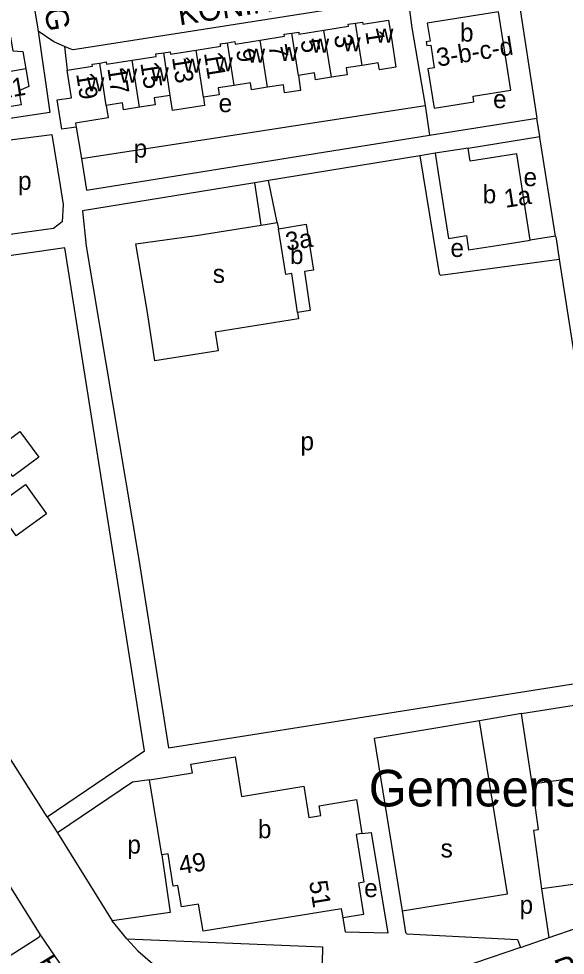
# Model space of a CAD drawing. Extents: x 159675 to 162108, y 386471 to 388472.
# Drawn here: x 160527.6 to 160647.4, y 386875.3 to 387080.5 of the extents above; entities that cross this region are included whole.
import ezdxf

# ---------------------------------------------------------------- set-up
doc = ezdxf.new("R2010")
doc.units = 0
for name, color, linetype in [('BLT_Basislijn', 7, 'Continuous'), ('BLT_Bebouwing', 7, 'Continuous'), ('BLT_Bebouwing_beschrifting', 7, 'Continuous'), ('BLT_Centroide', 7, 'Continuous'), ('BLT_Huisnummer', 7, 'Continuous'), ('BLT_Huisnummer_ tussenligend', 7, 'Continuous'), ('BLT_Huisnummer_reeks', 7, 'Continuous'), ('BLT_Onderverdeling_panden', 7, 'Continuous'), ('BLT_Straatnaam', 7, 'Continuous'), ('BLT_Vlakafsluiter', 7, 'Continuous')]:
    doc.layers.add(name, color=color, linetype=linetype)

msp = doc.modelspace()

# ---------------------------------------------------------------- linework, layer by layer
at = {"layer": 'BLT_Basislijn'}
for p, q in [((160537.63, 387074.35), (160538.2, 387069.22)), ((160541.3, 387049.83), (160616.69, 387061.42)), ((160616.69, 387061.42), (160617.66, 387054.93)), ((160540.15, 387056.72), (160541.3, 387049.83)), ((160617.66, 387054.93), (160641.18, 387058.71)), ((160641.8, 387054.69), (160641.18, 387058.71)), ((160626.09, 387052.12), (160641.8, 387054.69)), ((160618.89, 387051.01), (160615.55, 387050.46)), ((160615.55, 387050.46), (160582.31, 387045.02)), ((160582.31, 387045.02), (160579.33, 387044.54)), ((160584.25, 387035.83), (160582.31, 387045.02)), ((160580.71, 387035.26), (160584.25, 387035.83)), ((160584.25, 387035.83), (160584.54, 387034.45)), ((160645.29, 387032.81), (160639.7, 387031.95)), ((160646.04, 387027.79), (160660.27, 386936.54)), ((160637.8, 386928.26), (160660.96, 386931.98)), ((160640.15, 386912.84), (160637.8, 386928.26)), ((160533.79, 386905.62), (160536.05, 386902.11)), ((160536.05, 386902.11), (160548.06, 386882.84)), ((160643.91, 386879.19), (160642.29, 386889.86)), ((160551.24, 386878.93), (160548.06, 386882.84)), ((160637.62, 386877.04), (160643.91, 386879.19))]:
    msp.add_line(p, q, dxfattribs=at)
for points in [[(160525.82, 387114.65), (160525.96, 387113.82), (160528.15, 387100), (160531.84, 387077.71)], [(160612.92, 387085.16), (160631.58, 387088.2), (160635.7, 387088.25), (160636.9, 387086.77), (160641.18, 387058.71)], [(160612.92, 387085.16), (160539.47, 387073.63), (160538.99, 387073.76), (160537.63, 387074.35)], [(160612.92, 387085.16), (160613.78, 387078.48), (160616.69, 387061.42)], [(160531.84, 387077.71), (160534.38, 387059.89), (160513.51, 387056.76), (160514.73, 387049.16)], [(160537.63, 387074.35), (160535.24, 387075.38), (160531.84, 387077.71)], [(160536.69, 387043.96), (160537.33, 387039.73), (160537.06, 387035.97), (160535.21, 387034.49), (160522.41, 387032.72), (160519.35, 387053.09), (160534.86, 387055.11), (160536.69, 387043.96)], [(160541.3, 387049.83), (160542.44, 387042.9), (160617.66, 387054.93)], [(160645.29, 387032.81), (160641.84, 387054.43), (160641.8, 387054.69)], [(160615.55, 387050.46), (160619.76, 387024.57), (160620.02, 387024.3), (160646.04, 387027.79)], [(160579.33, 387044.54), (160541.58, 387038.36), (160542.39, 387030.6), (160553.88, 386962.03), (160560.43, 386920.74), (160660.27, 386936.54)], [(160588.73, 387016.11), (160588.95, 387014.72), (160570.67, 387011.82), (160571.31, 387007.69), (160557.43, 387005.49), (160555.72, 387016.54), (160553.27, 387031.17), (160566.47, 387032.97), (160580.71, 387035.26), (160580.4, 387037.26), (160579.33, 387044.54)], [(160645.29, 387032.81), (160645.38, 387032.21), (160646.04, 387027.79)], [(160533.79, 386905.62), (160555.12, 386920.11), (160537.7, 387030.3), (160500, 387024.88), (160461.83, 387019.07)], [(160533.79, 386905.62), (160515.13, 386934.8), (160500, 386958.89), (160461.83, 387019.07)], [(160637.8, 386928.26), (160628.58, 386926.69)], [(160628.58, 386926.69), (160605.53, 386922.76), (160611.64, 386885.01)], [(160611.64, 386885.01), (160634.73, 386888.75), (160628.58, 386926.69)], [(160505.85, 386921.44), (160507.66, 386919.05), (160532.28, 386879.76)], [(160556.25, 386913.76), (160552.5, 386913.2), (160536.05, 386902.11)], [(160643.91, 386879.19), (160645.32, 386879.67), (160662.54, 386885.53), (160665.02, 386887.2), (160665.65, 386887.94), (160666.08, 386888.6), (160667.09, 386892.03), (160665.4, 386903.23)], [(160602.82, 386901.96), (160604.84, 386902.22), (160608.49, 386880.15), (160599.2, 386880.34), (160598.68, 386883.49)], [(160558.92, 386897.27), (160560.78, 386884.7), (160548.06, 386882.84)], [(160611.64, 386885.01), (160612.41, 386880.27), (160612.66, 386880.01), (160636.93, 386878.73), (160637.62, 386877.04)], [(160532.28, 386879.76), (160531.96, 386879.22), (160509.46, 386864.89), (160508.91, 386864.54)], [(160551.24, 386878.93), (160553.72, 386876.27), (160558.48, 386872.1), (160561.42, 386869.96), (160570.27, 386865.5), (160581.17, 386862.81), (160588.59, 386862.35), (160593.86, 386862.86)], [(160551.24, 386878.93), (160594.19, 386877.18), (160593.86, 386862.86)], [(160637.62, 386877.04), (160598.11, 386863.6), (160593.86, 386862.86)]]:
    msp.add_lwpolyline(points, dxfattribs=at)
for points in [[(160522.1, 386985.83), (160527.79, 386990.06), (160532.01, 386984.39), (160526.31, 386980.16)], [(160522.38, 386973.66), (160529.03, 386978.46), (160533.69, 386971.99), (160527.03, 386967.2)]]:
    msp.add_lwpolyline(points, close=True, dxfattribs=at)
at = {"layer": 'BLT_Bebouwing'}
for p, q in [((160626.09, 387052.12), (160618.89, 387051.01)), ((160558.92, 386897.27), (160556.25, 386913.76))]:
    msp.add_line(p, q, dxfattribs=at)
for points in [[(160632.76, 387081.95), (160617.16, 387079.46), (160617.79, 387075.55), (160616.9, 387075.41), (160617.04, 387074.56), (160617.9, 387074.69), (160618.7, 387069.68), (160617.3, 387069.46), (160618.68, 387060.87), (160627.39, 387062.26), (160627.19, 387063.5), (160635.49, 387064.83), (160632.76, 387081.95)], [(160594.5, 387077.96), (160599.87, 387078.8), (160599.81, 387079.24), (160601.44, 387079.5)], [(160601.44, 387079.5), (160602.95, 387079.74), (160603.02, 387079.28), (160608.65, 387080.16), (160609.43, 387075.22), (160610.27, 387069.84), (160606.66, 387069.27), (160606.42, 387070.79), (160602.89, 387070.23)], [(160580.48, 387075.76), (160585.85, 387076.61), (160585.79, 387077.04), (160587.43, 387077.29)], [(160587.43, 387077.29), (160588.96, 387077.53), (160589.02, 387077.1), (160594.5, 387077.96)], [(160525.75, 387076.43), (160526.26, 387073.41), (160528.49, 387073.27), (160529.14, 387069.45)], [(160566.44, 387073.59), (160571.85, 387074.43), (160571.77, 387074.96), (160573.37, 387075.21)], [(160573.37, 387075.21), (160574.96, 387075.46), (160575.05, 387074.91), (160580.48, 387075.76)], [(160559.35, 387073.01), (160560.8, 387073.23), (160560.88, 387072.71), (160566.44, 387073.59)], [(160545.34, 387070.75), (160546.77, 387070.98), (160546.84, 387070.5), (160552.42, 387071.38)], [(160552.42, 387071.38), (160557.71, 387072.21), (160557.63, 387072.74), (160559.35, 387073.01)], [(160529.14, 387069.45), (160529.78, 387065.63), (160527.56, 387064.66), (160528.08, 387061.58), (160515.02, 387059.38), (160514.4, 387063.25), (160518.35, 387063.88), (160517.77, 387067.54)], [(160540.15, 387056.72), (160537.02, 387056.23), (160536.01, 387062.67), (160539.15, 387063.16), (160538.2, 387069.22)], [(160538.2, 387069.22), (160543.71, 387070.08), (160543.65, 387070.49), (160545.34, 387070.75)], [(160602.89, 387070.23), (160599.36, 387069.68), (160599.59, 387068.18), (160596.12, 387067.63)], [(160588.88, 387068.04), (160589.33, 387064.77), (160585.86, 387064.23), (160585.59, 387065.99), (160582.09, 387065.44)], [(160596.12, 387067.63), (160592.64, 387067.09), (160592.4, 387068.59), (160588.88, 387068.04)], [(160574.84, 387065.84), (160571.31, 387065.29), (160571.55, 387063.8), (160568.06, 387063.25)], [(160582.09, 387065.44), (160578.6, 387064.89), (160578.37, 387066.4), (160574.84, 387065.84)], [(160560.81, 387063.65), (160557.29, 387063.1), (160557.52, 387061.6), (160554.04, 387061.05)], [(160568.06, 387063.25), (160568.3, 387061.45), (160561.29, 387060.35), (160560.81, 387063.65)], [(160546.76, 387061.45), (160547.19, 387058.72), (160540.01, 387057.6), (160540.15, 387056.72)], [(160554.04, 387061.05), (160550.55, 387060.5), (160550.31, 387062.01), (160546.76, 387061.45)], [(160618.89, 387051.01), (160619.7, 387045.78), (160621.78, 387032.33), (160625.72, 387032.94), (160626.19, 387029.86), (160634.76, 387031.18), (160639.7, 387031.95)], [(160639.7, 387031.95), (160636.78, 387050.85), (160626.53, 387049.27), (160626.09, 387052.12)], [(160584.54, 387034.45), (160590.62, 387035.42), (160592.23, 387025.37), (160590.22, 387025.05)], [(160588.73, 387016.11), (160587.45, 387024.64), (160586.14, 387024.4), (160584.54, 387034.45)], [(160590.22, 387025.05), (160591.5, 387016.52), (160588.73, 387016.11)], [(160556.25, 386913.76), (160565.64, 386915.28), (160565.33, 386917.19), (160575.02, 386918.76), (160576.43, 386910.1), (160590.06, 386912.31), (160591.16, 386905.5), (160593.82, 386905.93), (160593.47, 386908.07), (160601.62, 386909.39), (160602.82, 386901.96)], [(160640.15, 386912.84), (160650.08, 386914.23), (160650.32, 386912.46), (160656.1, 386913.26), (160656.26, 386912.12), (160657.48, 386912.29)], [(160642.29, 386889.86), (160640.49, 386902.69), (160641.54, 386902.84), (160640.15, 386912.84)], [(160602.82, 386901.96), (160601.55, 386901.76), (160603.25, 386891.29), (160602.05, 386891.1), (160603.17, 386884.22), (160598.68, 386883.49)], [(160659.66, 386902.43), (160659.72, 386902.05), (160657.82, 386901.78), (160659.16, 386892.21), (160642.29, 386889.86)], [(160598.68, 386883.49), (160598.36, 386885.48), (160567.98, 386880.55), (160567.02, 386886.51), (160563.24, 386885.9), (160562.47, 386890.61), (160561.46, 386890.45), (160560.32, 386897.5), (160558.92, 386897.27)]]:
    msp.add_lwpolyline(points, dxfattribs=at)
at = {"layer": 'BLT_Onderverdeling_panden'}
for p, q in [((160602.89, 387070.23), (160601.44, 387079.5)), ((160588.88, 387068.04), (160587.43, 387077.29)), ((160596.12, 387067.63), (160594.5, 387077.96)), ((160574.84, 387065.84), (160573.37, 387075.21)), ((160582.09, 387065.44), (160580.48, 387075.76)), ((160568.06, 387063.25), (160566.44, 387073.59)), ((160554.04, 387061.05), (160552.42, 387071.38)), ((160560.81, 387063.65), (160559.35, 387073.01)), ((160529.14, 387069.45), (160517.77, 387067.54)), ((160546.76, 387061.45), (160545.34, 387070.75))]:
    msp.add_line(p, q, dxfattribs=at)
at = {"layer": 'BLT_Vlakafsluiter'}
msp.add_line((160532.28, 386879.76), (160539.78, 386868.77), dxfattribs=at)

# ---------------------------------------------------------------- texts
at = {"layer": 'BLT_Bebouwing_beschrifting'}
msp.add_text('Gemeenschapshuis', height=8, dxfattribs=at).set_placement((160604.33, 386907.91))
at = {"layer": 'BLT_Centroide'}
for s, p in [('b', (160624.33, 387075.44)), ('w', (160605.86, 387075.2)), ('w', (160591.77, 387073.02)), ('w', (160598.69, 387073.33)), ('w', (160577.73, 387070.81)), ('w', (160584.91, 387071.17)), ('w', (160563.7, 387068.62)), ('w', (160570.64, 387068.95)), ('w', (160549.69, 387066.42)), ('w', (160556.61, 387066.73)), ('w', (160542.5, 387064.58)), ('e', (160571.4, 387059.99)), ('e', (160631.58, 387060.88)), ('p', (160552.76, 387050.04)), ('e', (160638.26, 387043.78)), ('p', (160527.41, 387042.97)), ('b', (160629.3, 387040.02)), ('b', (160587.04, 387026.73)), ('e', (160622.23, 387028.27)), ('s', (160570.12, 387022.59)), ('p', (160589.35, 386985.92)), ('b', (160580.01, 386900.94)), ('p', (160551.39, 386897.57)), ('s', (160620.08, 386896.73)), ('e', (160603.31, 386888.03)), ('p', (160637.39, 386884.37))]:
    msp.add_text(s, height=4, dxfattribs=at).set_placement(p)
at = {"layer": 'BLT_Huisnummer'}
for s, rotation, p in [('1', 278.8999, (160603.56, 387077.65)), ('5', 278.8999, (160589.35, 387075.69)), ('9', 278.8999, (160575.21, 387073.61)), ('13', 278.8999, (160561.15, 387071.97)), ('21', 9.5477, (160523.43, 387062.83)), ('19', 278.8999, (160540.14, 387068.38)), ('1a', 8.7939, (160634.3, 387039.02)), ('3a', 9.0771, (160586.39, 387029.61))]:
    msp.add_text(s, height=4, rotation=rotation, dxfattribs=at).set_placement(p)
at = {"layer": 'BLT_Huisnummer_ tussenligend'}
for s, p in [('3', (160596.66, 387076.76)), ('7', (160582.33, 387074.59)), ('11', (160568.17, 387072.93)), ('17', (160546.99, 387069.6)), ('15', (160554.22, 387070.74))]:
    msp.add_text(s, height=4, rotation=278.8962, dxfattribs=at).set_placement(p)
at = {"layer": 'BLT_Huisnummer_reeks'}
for s, rotation, p in [('3-b-c-d', 9.0771, (160619.49, 387069.95)), ('49', 9.2178, (160563.01, 386893)), ('51', 279.2114, (160591.22, 386891.41))]:
    msp.add_text(s, height=4, rotation=rotation, dxfattribs=at).set_placement(p)
at = {"layer": 'BLT_Straatnaam'}
for s, height, rotation, p in [('KONING MARKWEG', 4.9999, 279.4042, (160523.63, 387140.08)), ('KONING MARKWEG', 5, 8.7398, (160562.81, 387078.99)), ('KONING ARTHURLAAN', 5, 19.8279, (160615.5, 386858.17)), ('REYNHOVESTRAAT', 5, 31.1301, (160483.35, 386838.34))]:
    msp.add_text(s, height=height, rotation=rotation, dxfattribs=at).set_placement(p)

doc.saveas('drawing.dxf')
